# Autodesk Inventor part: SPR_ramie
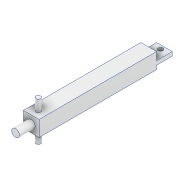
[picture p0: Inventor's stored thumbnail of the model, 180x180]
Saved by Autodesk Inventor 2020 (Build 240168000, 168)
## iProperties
Created: 2021-01
Part Number: SPR_ramie
Material: Aluminium 6061
Document SubType Name: Modeling
Designer: Home
Density: 2.7 g/cm^3
Appearance: Aluminium — płaski
Mass: 173.55 g
Surface Area: 150.315 cm^2
Volume: 64.2777 cm^3
Author: Home
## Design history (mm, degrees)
sketch "Szkic1"
  geometry: L1 (-10, -10)-(10, -10); L2 (10, -10)-(10, 10); L3 (10, 10)-(-10, 10); L4 (-10, 10)-(-10, -10); L5 (-10, -10)-(10, 10); L6 (10, -10)-(-10, 10); 1 further point
  constraints: 12 end point, 2 midpoint, 2 parallel, 1 horizontal, 1 perpendicular
  dimensions: "d0" = 20 distance of L3.end L2.end; "d1" = 20 distance of L2.end L1.end
extrude "Wyciągnięcie proste1" new body sketch "Szkic1" distance "d2" = 150; taper "d3" = 0 deg
sketch "Szkic2"
  geometry: L1 (-10, 150)-(10, 150) reference; C1 r 3 at (0, 141); 1 further point
  constraints: 1 centre point
  dimensions: "d4" = 6 diameter of C1; "d18" = 9 distance from line of L1 C1.centre
extrude "Wyciągnięcie proste2" join sketch "Szkic2" stored distance "d5" = 50; taper "d6" = 0 deg
sketch "Szkic3"
  geometry: L1 (0, 0)-(-5, 0); L2 (-5, 0)-(-5, -20); L3 (-5, -20)-(0, -20); L4 (0, -20)-(0, 0)
  constraints: 8 end point, 2 parallel, 1 horizontal, 1 perpendicular
  dimensions: "d7" = 5 distance of L3.end L2.end; "d8" = 20 distance of L2.end L1.end
extrude "Wyciągnięcie proste3" join sketch "Szkic3" stored distance "d9" = 20; taper "d10" = 0 deg
sketch "Szkic4"
  geometry: L1 (0, 0)-(20, 0) reference; L2 (20, -20)-(0, -20) reference; C1 r 3 at (10, -5); 2 further points
  constraints: 1 centre point, 1 midpoint, 1 vertical alignment
  dimensions: "d11" = 6 diameter of C1; "d12" = 5 distance from line of L1 C1.centre
extrude "Wyciągnięcie proste4" cut sketch "Szkic4" extent not by distance; stored distance "d13" = 0; taper "d14" = 0 deg
sketch "Szkic5"
  geometry: C1 r 5 at (0, 0); 1 further point
  constraints: 1 centre point, 1 coincident
  dimensions: "d15" = 10 diameter of C1
extrude "Wyciągnięcie proste5" join sketch "Szkic5" distance "d16" = 20; taper "d17" = 0 deg
node "Bryła1"
